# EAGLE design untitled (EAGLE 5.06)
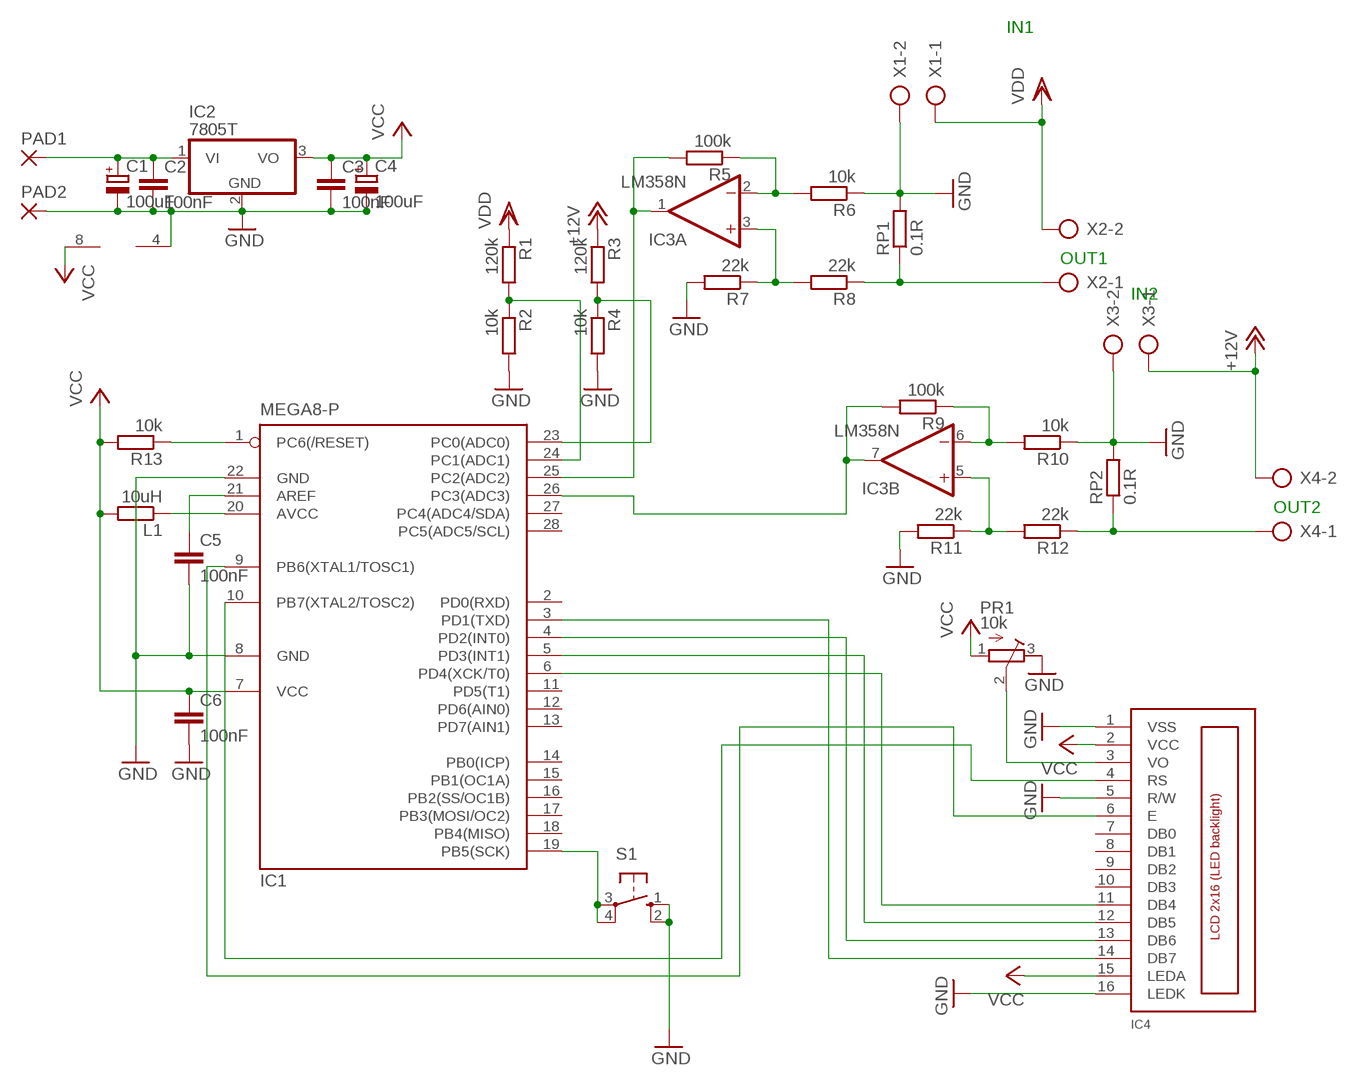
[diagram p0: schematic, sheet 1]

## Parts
C1  100uF  CPOL-EUE2-4  [E2-4]
C2  100nF  C-EU025-025X050  [C025-025X050]
C3  100nF  C-EU025-025X050  [C025-025X050]
C4  100uF  CPOL-EUE2-4  [E2-4]
C5  100nF  C-EU025-025X050  [C025-025X050]
C6  100nF  C-EU025-025X050  [C025-025X050]
IC1  MEGA8-P  [DIL28-3]
IC2  7805T  [TO220H]
IC3  LM358N  [DIL08]
IC4  LCD_2X16_SIL  [HY-1602F]
L1  10uH  R-EU_0204/2V  [0204V]
PAD1  3,17/1,3  [3,17/1,3]
PAD2  3,17/1,3  [3,17/1,3]
PR1  10k  R-TRIMM3339P  [RTRIM3339P]
R1  120k  R-EU_0207/7  [0207/7]
R2  10k  R-EU_0207/7  [0207/7]
R3  120k  R-EU_0207/7  [0207/7]
R4  10k  R-EU_0207/7  [0207/7]
R5  100k  R-EU_0207/7  [0207/7]
R6  10k  R-EU_0207/7  [0207/7]
R7  22k  R-EU_0207/7  [0207/7]
R8  22k  R-EU_0207/7  [0207/7]
R9  100k  R-EU_0207/7  [0207/7]
R10  10k  R-EU_0207/7  [0207/7]
R11  22k  R-EU_0207/7  [0207/7]
R12  22k  R-EU_0207/7  [0207/7]
R13  10k  R-EU_0207/7  [0207/7]
RP1  0.1R  R-EU_0617/22  [0617/22]
RP2  0.1R  R-EU_0617/22  [0617/22]
S1  10-XX  [B3F-10XX]
X1  AK300/2  [AK300/2]
X2  AK300/2  [AK300/2]
X3  AK300/2  [AK300/2]
X4  AK300/2  [AK300/2]

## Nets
+12V: R3.1 X3.1 X4.2
GND: C1.- C2.2 C3.2 C4.- C5.2 C6.2 IC1.8(GND) IC1.22(GND) IC2.2(GND) IC3.4(P:V-) IC4.1(VSS) IC4.5(R/W) IC4.16(LEDK) PAD2.1(P) PR1.3(A) R2.2 R4.2 R6.1 R7.2 R10.1 R11.2 RP1.2 RP2.2 S1.1(S) S1.2(S1) X1.2 X3.2
N$1: IC4.3(VO) PR1.2(S)
N$2: IC1.4(PD2(INT0)) IC4.13(DB6)
N$3: IC1.10(PB7(XTAL2/TOSC2)) IC4.4(RS)
N$5: IC1.6(PD4(XCK/T0)) IC4.11(DB4)
N$6: IC1.5(PD3(INT1)) IC4.12(DB5)
N$7: IC1.3(PD1(TXD)) IC4.14(DB7)
N$8: IC1.23(PC0(ADC0)) R3.2 R4.1
N$9: C5.1 IC1.21(AREF)
N$10: IC1.1(PC6(/RESET)) R13.1
N$11: IC1.25(PC2(ADC2)) IC3.1(A:OUT) R5.2
N$12: IC1.20(AVCC) L1.1
N$14: IC3.2(A:-IN) R5.1 R6.2
N$15: IC1.19(PB5(SCK)) S1.3(P) S1.4(P1)
N$16: C1.+ C2.1 IC2.1(VI) PAD1.1(P)
N$17: IC3.3(A:+IN) R7.1 R8.2
N$18: R8.1 RP1.1 X2.1
N$19: IC3.6(B:-IN) R9.1 R10.2
N$20: IC1.9(PB6(XTAL1/TOSC1)) IC4.6(E)
N$21: R12.1 RP2.1 X4.1
N$22: IC1.26(PC3(ADC3)) IC3.7(B:OUT) R9.2
N$24: IC3.5(B:+IN) R11.1 R12.2
N$62: IC1.24(PC1(ADC1)) R1.2 R2.1
VCC: C3.1 C4.+ C6.1 IC1.7(VCC) IC2.3(VO) IC3.8(P:V+) IC4.2(VCC) IC4.15(LEDA) L1.2 PR1.1(E) R13.2
VDD: R1.1 X1.1 X2.2
Unconnected: IC1.2(PD0(RXD)) IC1.11(PD5(T1)) IC1.12(PD6(AIN0)) IC1.13(PD7(AIN1)) IC1.14(PB0(ICP)) IC1.15(PB1(OC1A)) IC1.16(PB2(SS/OC1B)) IC1.17(PB3(MOSI/OC2)) IC1.18(PB4(MISO)) IC1.27(PC4(ADC4/SDA)) IC1.28(PC5(ADC5/SCL)) IC4.7(DB0) IC4.8(DB1) IC4.9(DB2) IC4.10(DB3)

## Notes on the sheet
- IN1
- OUT1
- IN2
- OUT2

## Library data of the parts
C1 C4 = rcl:CPOL-EU: POLARIZED CAPACITOR, European symbol
C2 C3 C5 C6 = rcl:C-EU: CAPACITOR, European symbol
IC1 = atmel:MEGA8-P: MICROCONTROLLER 8 Kbytes FLASH, 1 kbytes SRAM, 512 bytes EEPROM, USART, 4-channel 10 bit ADC, 2-channel 8 bit ADC Pin compatible with Atmega48, ATMega88, ATMega168 Source: avr.lbr
IC2 = linear:78*: Positive VOLTAGE REGULATOR Source: http://cache.national.com/ds/LM/LM78L05.pdf http://www.fairchildsemi.com/ds/LM/LM7805.pdf
IC3 = linear:LM358: OP AMP also LM158; LM258; LM2904 Source: http://cache.national.com/ds/LM/LM158.pdf
IC4 = lcd_2x16_led_backlight:LCD_2X16_SIL
L1 R1-R13 RP1 RP2 = rcl:R-EU_: RESISTOR, European symbol
PAD1 PAD2 = wirepad:3,17/1,3: THROUGH-HOLE PAD
PR1 = rcl:R-TRIMM: Trimm resistor
S1 = switch-omron:10-XX: OMRON SWITCH
X1-X4 = con-ptr500:AK300/2: CONNECTOR

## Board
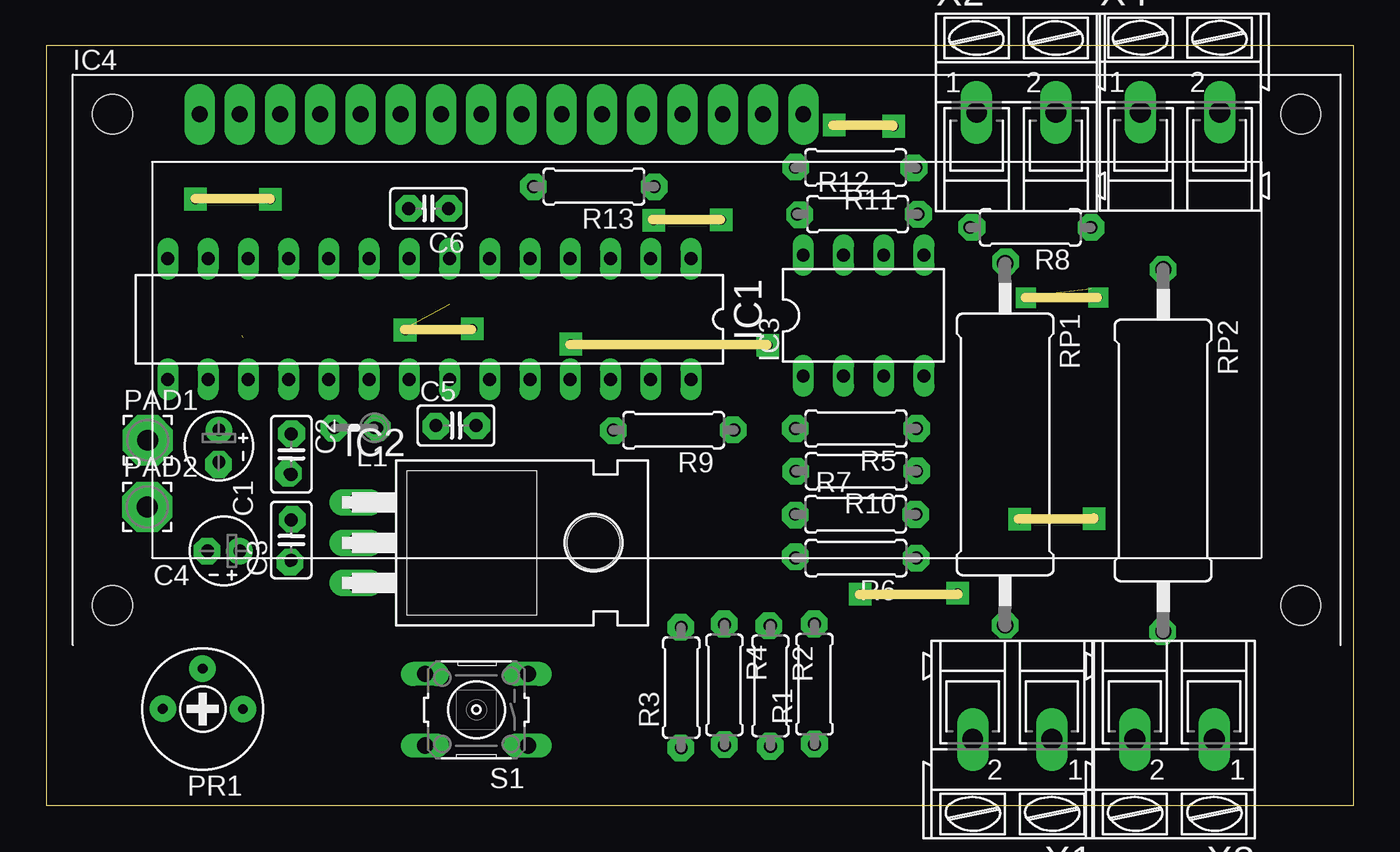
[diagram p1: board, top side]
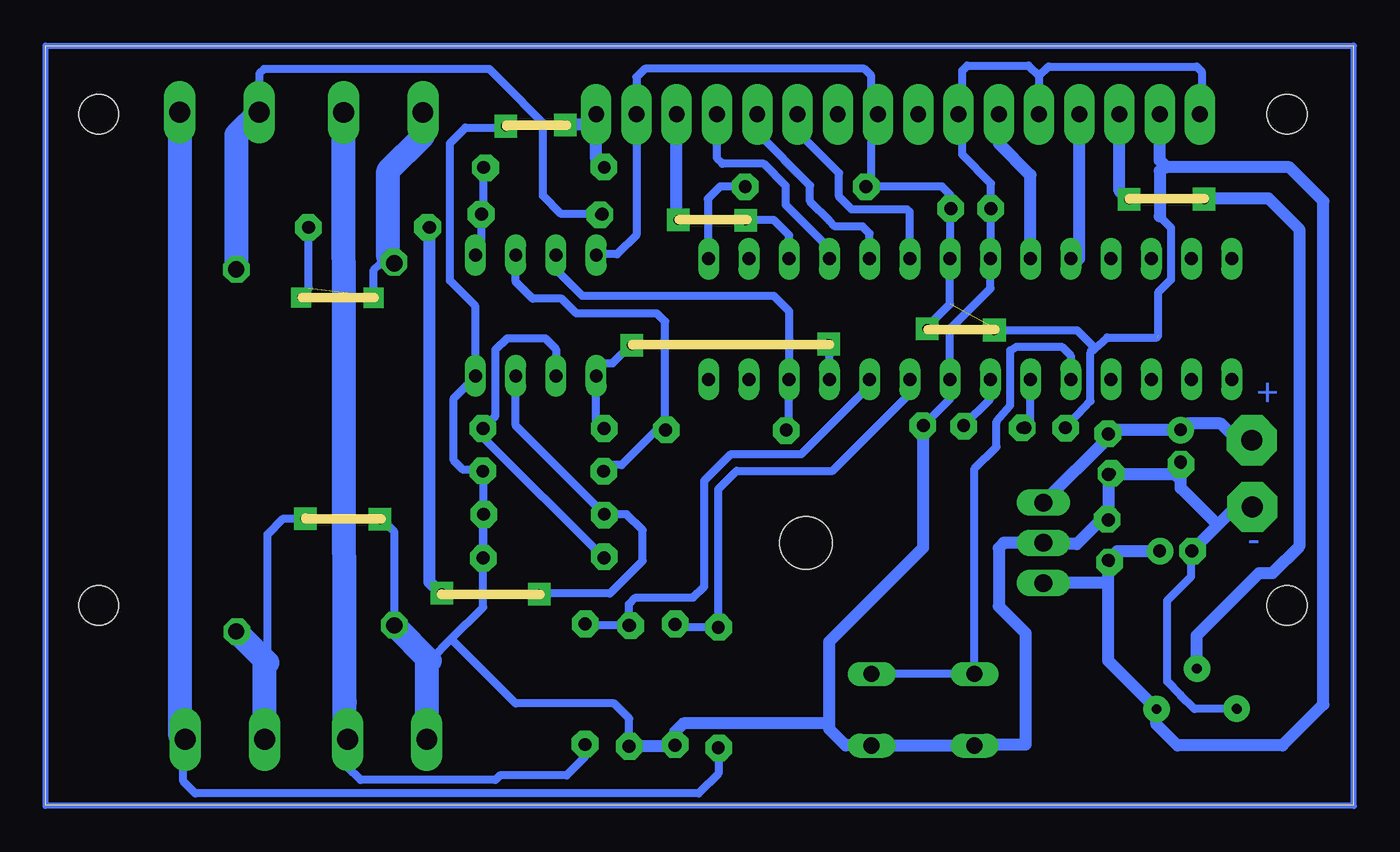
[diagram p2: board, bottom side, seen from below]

Size 82.53 x 47.93 mm. Coordinates in mm from the lower left corner, seen from the top.
Outline: 61.35,18.07 66.13,18.07 66.13,18.13
Outline: 61.79,32.04 66.33,32.04 66.33,32.05
Outline: 9.39,38.27 14.13,38.27 14.13,38.26
Outline: 38.27,36.95 42.54,36.95
Outline: 22.62,30.04 26.84,30.04
Outline: 33.05,29.07 45.49,29.07 45.49,29.04
Outline: 49.64,42.91 53.44,42.91 53.44,42.87
Outline: 51.32,13.31 57.54,13.31 57.54,13.34
Outline: 0,0 82.53,0 82.53,47.93 0,47.93 0,0
Copper layers (1*16): Top 0.035mm / dielectric 1.5mm / Bottom 0.035mm
Design rules "default": minimum track width 10mil, minimum drill 24mil, track to track 8mil, track to pad 8mil, pad to pad 8mil, via to via 8mil, smd to smd 8mil, copper to edge 40mil, drill to drill 8mil, minimum pad ring 10mil, minimum via ring 8mil, stop-mask expansion 4mil, vias tented up to drill 0mil, thermal gap 10mil

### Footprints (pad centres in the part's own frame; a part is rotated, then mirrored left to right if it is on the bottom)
E2-4 = drill 0.813 pad 1.27 round: + -1.016,0 | drill 0.813 pad 1.27 octagon: - 1.016,0
C025-025X050 = drill 0.813 octagon: 1 -1.27,0; 2 1.27,0
DIL28-3 = drill 0.813 long: 1 -16.51,-3.81; 2 -13.97,-3.81; 3 -11.43,-3.81; 4 -8.89,-3.81; 5 -6.35,-3.81; 6 -3.81,-3.81; 7 -1.27,-3.81; 8 1.27,-3.81; 9 3.81,-3.81; 10 6.35,-3.81; 11 8.89,-3.81; 12 11.43,-3.81; 13 13.97,-3.81; 14 16.51,-3.81; 15 16.51,3.81; 16 13.97,3.81; 17 11.43,3.81; 18 8.89,3.81; 19 6.35,3.81; 20 3.81,3.81; 21 1.27,3.81; 22 -1.27,3.81; 23 -3.81,3.81; 24 -6.35,3.81; 25 -8.89,3.81; 26 -11.43,3.81; 27 -13.97,3.81; 28 -16.51,3.81
TO220H = drill 1.118 long: 1 -2.54,-10.16; 2 0,-10.16; 3 2.54,-10.16 | hole 3.302: 0,4.826
DIL08 = drill 0.813 long: 1 -3.81,-3.81; 2 -1.27,-3.81; 3 1.27,-3.81; 4 3.81,-3.81; 5 3.81,3.81; 6 1.27,3.81; 7 -1.27,3.81; 8 -3.81,3.81
HY-1602F = drill 1 pad 1.93 long: 1 2.54,0; 2 5.08,0; 3 7.62,0; 4 10.16,0; 5 12.7,0; 6 15.24,0; 7 17.78,0; 8 20.32,0; 9 22.86,0; 10 25.4,0; 11 27.94,0; 12 30.48,0; 13 33.02,0; 14 35.56,0; 15 38.1,0; 16 40.64,0 | hole 2.5: -2.96,0; 72.04,0; -2.96,-31; 72.04,-31
0204V = drill 0.813 octagon: 1 -1.27,0; 2 1.27,0
3,17/1,3 = drill 1.321 pad 3.175 octagon: 1 0,0
RTRIM3339P = drill 0.61 round: 1 -2.54,0; 2 0,-2.54; 3 2.54,0
0207/7 = drill 0.813 octagon: 1 -3.81,0; 2 3.81,0
0617/22 = drill 1.016 octagon: 1 -11.43,0; 2 11.43,0
B3F-10XX = drill 1.016 long: 1 -3.251,2.261; 2 3.251,2.261; 3 -3.251,-2.261; 4 3.251,-2.261
AK300/2 = drill 1.321 long: 1 -2.515,0; 2 2.489,0

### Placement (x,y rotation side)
C1  10.9,22.68 270 top
C2  15.47,22.15 270 top
C3  15.47,16.74 90 top
C4  11.21,16.04 180 top
C5  25.86,23.97 0 top
C6  24.13,37.67 180 top
IC1  24.18,30.68 180 top
IC2  29.72,16.56 270 top
IC3  51.59,30.91 0 top
IC4  7.14,43.61 0 top
L1  19.45,23.82 180 top
PAD1  6.4,23.04 0 top
PAD2  6.38,18.82 0 top
PR1  9.88,6.07 180 top
R1  48.49,7.63 90 top
R2  45.71,7.53 270 top
R3  40.08,7.42 90 top
R4  42.8,7.59 270 top
R5  51.1,23.77 180 top
R6  51.1,15.6 180 top
R7  51.08,18.36 0 top
R8  62.11,36.47 180 top
R9  39.6,23.67 180 top
R10  51.13,21.08 180 top
R11  51.08,40.26 180 top
R12  51.21,37.31 0 top
R13  34.57,39.05 180 top
RP1  60.52,22.77 270 top
RP2  70.49,22.39 270 top
S1  27.15,6.02 180 top
X1  60.96,4.15 180 top
X2  61.23,43.73 0 top
X3  71.2,4.15 180 top
X4  71.57,43.75 0 top

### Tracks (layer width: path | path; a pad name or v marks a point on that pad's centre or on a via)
+12V
  Bottom 0.508: R3.1 40.08,1.98 41.31,0.75 73.08,0.75 73.85,1.52 73.85,4.01 X3.1
  Bottom 1.524: X4.2 74.06,4.5 X3.1
GND  (2 unrouted)
  Bottom 0.508: 19.84,46.03 IC4.5 | 19.84,46.03 19.24,46.63 9.88,46.63 9.56,46.31 9.56,43.73 IC4.1 | 19.84,46.03 20.49,46.69 24.36,46.69 24.68,46.37 24.68,41.07 22.86,39.25 C6.2 22.86,34.54 IC1.8 22.89,34.48 22.89,32.62 25.45,30.06 IC1.22 25.45,25.65 C5.2 | 54.91,18.34 R6.1 | 54.91,18.34 R7.2 54.89,21.03 R10.1 55.03,21.17 56.17,21.17 56.78,21.77 56.78,25.67 55.4,27.05 IC3.4 55.4,31.49 57.01,33.11 57.01,41.79 56.03,42.77 53.66,42.77 53.46,42.97 | R4.2 42.86,3.72 | 60.77,11.51 60.6,11.34 RP1.2 60.52,17.24 61.37,18.1 | 9.68,16.56 C4.- 10.22,16.01 10.22,14.44 11.74,12.92 11.74,7.81 10.9,6.98 10.9,6.95 10.03,6.07 PR1.3 | 68.53,9 68.53,17.1 67.53,18.1 66.18,18.1 66.15,18.06 | 54.91,18.34 54.91,12.5 56.93,10.48 | 56.93,10.48 58.29,9.12 | R2.2 45.71,5.47 46.65,6.41 52.86,6.41 56.93,10.48
  Bottom 0.762: PAD2.1 7.42,18.82 8.56,17.68 | 9.68,16.56 8.56,17.68 | 10.9,20.53 10.9,20.02 8.56,17.68 | 10.9,20.53 C1.- | 10.9,20.53 11.25,20.88 C2.2 C3.2 15.93,18.01 17.45,16.48 19.48,16.48 IC2.2 22.05,16.56 22.38,16.23 22.38,12.55 20.69,10.86 20.69,3.83 20.68,3.82 23.84,3.82 S1.2 S1.1 30.41,3.77 32.04,3.77 33.07,4.79 33.07,5.15 33.24,5.15 | R4.2 42.8,4.64 42.28,5.15 33.24,5.15 | 45.7,3.73 R2.2 42.86,3.72 | R11.2 47.78,40.77 IC4.16 47.78,43.14 47.95,42.97 49.64,42.97 | C5.2 27.13,16.27 33.07,10.33 33.07,5.33 33.24,5.15
  Bottom 1.524: RP2.2 68.53,9 68.71,8.82 X3.2 | X1.2 58.47,8.94 58.29,9.12 RP1.2
N$1  (1 unrouted)
  Bottom 0.762: IC4.3 14.76,38.77 14.28,38.29 | PR1.2 9.88,10.72 5.94,14.66 5.11,14.66 3.39,16.38 3.39,36.33 5.34,38.29 9.34,38.29
N$2
  Bottom 0.508: IC4.13 40.16,40.82 39.82,40.49 37.2,40.49 35.81,39.09 35.81,37.88 34.57,36.64 33.07,35.14 IC1.4
N$3
  Bottom 0.762: IC1.10 17.3,34.49 IC4.4
N$4  (via drill 0.6 pad 1.42)
  other vias: 51.36,13.31
N$5
  Bottom 0.508: IC4.11 35.08,42.53 32.45,39.91 32.45,38.41 31.65,37.61 28.15,37.61 28,37.46 IC1.6
N$6
  Bottom 0.508: IC4.12 37.62,42.47 34.27,39.12 34.27,38.1 33.07,36.89 | 33.07,36.89 | 33.07,36.89 32.71,36.54 30.97,36.54 30.53,36.09 IC1.5 | IC1.5
N$7  (1 unrouted)
  Bottom 0.508: IC1.3 35.61,35.98 36.58,36.94 38.31,36.94
  Bottom 0.762: IC4.14 42.7,37.14 42.5,36.94
N$8
  Bottom 0.508: R4.1 42.63,11.23 R3.2 40.07,11.24 40.07,19.96 38.92,21.1 32.86,21.1 27.99,25.97 IC1.23
N$9
  Bottom 0.508: IC1.21 22.91,25.65 C5.1
N$10
  Bottom 0.508: R13.1 39.97,39.05 40.74,38.28 40.74,34.54 IC1.1
N$11  (1 unrouted)
  Bottom 0.508: R5.2 47.78,24.26 IC3.1 47.72,27.16 47.72,27.91 46.74,27.91 45.56,29.09 | IC1.25 33.07,29.09 | 33.07,29.09
N$12
  Bottom 0.508: IC1.20 20.37,24.17 L1.1
N$13  (via drill 0.6 pad 1.42)
  other vias: 57.52,13.38
N$14
  Bottom 0.508: R6.2 54.91,23.22 R5.1 54.14,24.58 54.14,28.75 53.38,29.48 51.01,29.48 50.32,28.79 IC3.2
N$15
  Bottom 0.508: S1.3 S1.4 23.9,21.24 22.52,22.62 22.52,24.21 21.64,25.24 21.64,28.71 21.26,28.95 18.4,28.95 17.83,28.38 IC1.19
N$16
  Bottom 0.762: PAD1.1 7.32,23.04 8.36,24.08 10.51,24.08 C1.+ 15.19,23.7 C2.1 15.47,23.19 IC2.1
N$17  (1 unrouted)
  Bottom 0.508: IC3.3 52.86,23.95 R7.1 45.86,18.36 44.86,17.36 44.86,15.42 46.92,13.36 51.4,13.36
  Bottom 0.762: R8.2 58.3,14.09 57.56,13.35
N$18  (1 unrouted)
  Bottom 0.508: R8.1 65.92,32.62 66.42,32.12 | RP1.1 61.39,34.2 61.85,33.74 61.85,32.15 61.8,32.1
  Bottom 1.524: X2.1 58.72,42.24 60.91,40.05 60.91,34.6 RP1.1
N$19
  Bottom 0.508: R10.2 46.93,21.47 46.17,21.47 43.97,23.67 R9.1 43.44,23.7 43.44,30.53 43.95,31.04 49.03,31.04 49.96,31.98 51.79,31.98 52.86,33.05 IC3.6
N$20
  Bottom 0.762: IC4.6 22.38,41.79 20.36,39.78 IC1.9
N$21
  Bottom 0.508: R12.1 49.99,37.31 51.14,38.46 51.14,43.06 52.4,44.32 52.4,44.34 54.53,46.47 68.74,46.47 69.05,46.16 X4.1
  Bottom 1.524: RP2.1 70.49,42.31 X4.1
N$22
  Bottom 0.508: R9.2 35.61,23.85 IC1.26 35.6,26.89 35.6,31.17 36.57,32.15 48.65,32.15 50.32,33.81 IC3.7
N$23  (via drill 0.6 pad 1.42)
  other vias: 53.48,42.86
N$24
  Bottom 0.508: R11.1 54.89,37.44 R12.2 55.02,35.1 IC3.5
N$25  (via drill 0.6 pad 1.68)
  other vias: 54.94,23.78
N$26  (via drill 0.6 pad 1.68)
  other vias: 54.94,21.1
N$27  (via drill 0.6 pad 1.68)
  other vias: 54.87,18.35
N$28  (via drill 0.6 pad 1.68)
  other vias: 54.91,15.58
N$29  (via drill 0.6 pad 1.68)
  other vias: 35.8,23.64
N$30  (via drill 0.6 pad 1.68)
  other vias: 43.36,23.69
N$31  (via drill 0.6 pad 1.68)
  other vias: 47.28,23.78
N$32  (via drill 0.6 pad 1.68)
  other vias: 47.3,21.08
N$33  (via drill 0.6 pad 1.68)
  other vias: 47.28,18.31
N$34  (via drill 0.6 pad 1.68)
  other vias: 47.28,15.7
N$35  (via drill 0.6 pad 1.68)
  other vias: 30.74,39.04
N$36  (via drill 0.6 pad 1.68)
  other vias: 38.38,39.04
N$37  (via drill 0.6 pad 1.42)
  other vias: 49.74,42.94
N$38  (via drill 0.6 pad 1.68)
  other vias: 47.29,40.29
N$39  (via drill 0.6 pad 1.68)
  other vias: 54.76,40.23
N$40  (via drill 0.6 pad 1.68)
  other vias: 55.05,37.3
N$41  (via drill 0.6 pad 1.68)
  other vias: 47.55,37.27
N$42  (via drill 0.6 pad 1.68)
  other vias: 65.95,36.47
N$43  (via drill 0.6 pad 1.68)
  other vias: 58.42,36.48
N$44  (via drill 0.6 pad 1.68)
  other vias: 60.55,34.3
N$45  (via drill 0.6 pad 1.68)
  other vias: 70.48,33.82
N$46  (via drill 0.6 pad 1.68)
  other vias: 60.53,11.36
N$47  (via drill 0.6 pad 1.68)
  other vias: 70.45,10.95
N$48  (via drill 0.6 pad 1.68)
  other vias: 15.28,20.94
N$49  (via drill 0.6 pad 1.68)
  other vias: 15.53,18.04
N$50  (via drill 0.6 pad 1.68)
  other vias: 15.39,15.33
N$51  (via drill 0.6 pad 1.42)
  other vias: 42.61,36.94
N$52  (via drill 0.6 pad 1.68)
  other vias: 10.88,21.51
N$53  (via drill 0.6 pad 1.42)
  other vias: 38.34,36.93
N$54  (via drill 0.6 pad 1.42)
  other vias: 14.16,38.24
N$55  (via drill 0.6 pad 1.68)
  other vias: 22.9,37.67
N$56  (via drill 0.6 pad 1.68)
  other vias: 25.42,37.67
N$57  (via drill 0.6 pad 1.42)
  other vias: 9.43,38.26
N$58  (via drill 0.6 pad 1.42)
  other vias: 22.65,29.99
N$59  (via drill 0.6 pad 1.68)
  other vias: 12.41,6.07
N$60  (via drill 0.6 pad 1.68)
  other vias: 9.86,8.61
N$61  (via drill 0.6 pad 1.68)
  other vias: 7.37,6.09
N$62
  Bottom 0.508: R2.1 48.39,11.34 R1.2 | IC1.24 30.53,26.46 34.83,22.16 39.27,22.16 40.95,20.48 40.95,13.81 41.66,13.1 45.3,13.1 45.72,12.68 45.72,11.35 R2.1 | R2.1
N$63  (via drill 0.6 pad 1.42)
  other vias: 26.89,30.07
N$64  (via drill 0.6 pad 1.42)
  other vias: 33.09,29.11
N$65  (via drill 0.6 pad 1.42)
  other vias: 45.52,29.04
N$66
  Bottom 0.381: -0.03,47.95 82.53,47.95 82.53,-0.05 -0.04,-0.05 -0.04,47.93
N$67  (via drill 0.7 pad 1.68)
  other vias: 10.91,23.68
N$68  (via drill 0.6 pad 1.42)
  other vias: 66.13,18.09
N$69  (via drill 0.6 pad 1.42)
  other vias: 61.42,18.05
N$70  (via drill 0.7 pad 1.68)
  other vias: 40.05,3.61
N$71  (via drill 0.7 pad 1.68)
  other vias: 42.8,3.83
N$72  (via drill 0.7 pad 1.68)
  other vias: 45.69,3.71
N$73  (via drill 0.7 pad 1.68)
  other vias: 48.48,3.87
N$74  (via drill 0.7 pad 1.68)
  other vias: 48.47,11.44
N$75  (via drill 0.7 pad 1.68)
  other vias: 45.6,11.33
N$76  (via drill 0.7 pad 1.68)
  other vias: 42.78,11.44
N$77  (via drill 0.7 pad 1.68)
  other vias: 40.05,11.23
N$78  (via drill 0.7 pad 1.68)
  other vias: 20.91,23.81
N$79  (via drill 0.7 pad 1.68)
  other vias: 18.15,23.8
N$80  (via drill 0.7 pad 1.68)
  other vias: 24.58,23.91
N$81  (via drill 0.7 pad 1.68)
  other vias: 27.18,23.96
N$82  (via drill 0.5 pad 1.27)
  other vias: 61.84,32.03
N$83  (via drill 0.5 pad 1.27)
  other vias: 66.4,32.04
N$84  (via drill 0.7 pad 1.68)
  other vias: 15.49,23.46
N$85  (via drill 0.7 pad 1.68)
  other vias: 10.15,16.04
N$86  (via drill 0.7 pad 1.68)
  other vias: 12.2,16.04
VCC  (2 unrouted)
  Bottom 0.508: IC3.8 47.73,34.77 46.45,34.77 45.24,35.99 IC4.15 45.24,45.96 44.72,46.48 30.86,46.48 30.42,46.04 30.42,39.39 R13.2 25.96,39.05 25.42,38.51 25.42,37.68 | 25.42,37.68 C6.1 | 12.22,37.16 11.51,36.45 11.51,33.16 12.32,32.35 12.32,29.63 | 12.39,29.53 15.53,29.53 16.59,28.56 | 16.59,28.56 16.59,25.5 L1.2 | 16.59,28.56 16.38,28.92 17.43,29.97 22.55,29.97 22.72,30.14 | 25.42,37.68 25.42,34.53 IC1.7 25.45,31.62 26.94,30.13
  Bottom 0.762: C4.+ 14.89,16.04 C3.1 15.47,14.25 | 15.47,14.25 15.47,9.12 PR1.1 12.42,5.1 11.09,3.77 4.47,3.77 1.88,6.36 1.88,38.12 4.03,40.27 11.78,40.27 | IC2.3 15.7,14.02 15.47,14.25 | 11.78,40.27 11.98,40.27 12.22,40.04 12.22,37.16 | IC4.2 12.22,40.71 11.78,40.27
VDD
  Bottom 0.508: R1.1 48.49,3.04 49.65,1.88 53.86,1.88 54.14,1.59 62.66,1.59 63.46,2.39 63.46,4.13 X1.1
  Bottom 1.524: X2.2 63.65,6.5 63.65,4.32 X1.1
(copper drawn outside any net)
  shapes: Bottom circle x5

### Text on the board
Bottom: + | -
